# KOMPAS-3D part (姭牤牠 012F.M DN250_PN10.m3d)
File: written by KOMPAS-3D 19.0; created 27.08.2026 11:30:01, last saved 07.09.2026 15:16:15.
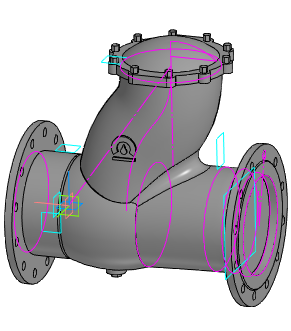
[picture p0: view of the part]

Document properties: Автор: Энергия; Полное имя файла: Z:\3.Личные\kachalov\001_3d для проектировщиков\х.х Тип 012F\012F.M\Клапан 012F.M DN250_PN10.m3d

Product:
- Part/product: (unnamed)  | designation Клапан 012F.M DN250_PN10
    Масса: 181.704

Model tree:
1. Эскиз:1
2. Элемент вращения:1
     Угол 1 = 360
3. Эскиз:2  (with: Элемент вращения:1)
4. Параллельная плоскость:3
5. Эскиз:26
6. Эскиз:30
7. Смещенная плоскость:5
     Расстояние = 150
8. Эскиз:50
9. Эскиз:51
10. Элемент по траектории:1
     Толщина стенки 1 = 1
11. Эскиз:31  (with: Элемент вращения:1)
12. Эскиз:38  (with: Элемент вращения:1)
13. Параллельная плоскость:4
14. Смещенная плоскость:2  (with: Элемент вращения:1)
     Расстояние = 32
15. Эскиз:39  (with: Элемент вращения:1)
16. Эскиз:40  (with: Элемент вращения:1)
17. Смещенная плоскость:3
     Расстояние = 33
18. Эскиз:42  (with: Элемент вращения:1)
19. Элемент по сечениям:4
20. Элемент вращения:6  (with: Элемент вращения:1)
     Угол 1 = 360
21. Эскиз:10  (with: Элемент вращения:1)
22. Элемент выдавливания:3  (with: Элемент вращения:1)
     Расстояние 2 = 19
23. Массив по концентрической сетке:1  (with: Элемент выдавливания:3, Эскиз:10, Элемент вращения:1)  (12 pattern instances)
     Шаг 2 = 360
24. Эскиз:11  (with: Элемент вращения:1)
25. Элемент выдавливания:4  (with: Элемент вращения:1)
     Расстояние 2 = 19
26. Массив по концентрической сетке:2  (with: Элемент выдавливания:4, Эскиз:11, Элемент вращения:1)  (12 pattern instances)
     Шаг 2 = 360
27. Эскиз:32
28. Элемент выдавливания:13
     Расстояние 1 = 25
29. Эскиз:33  (with: Элемент выдавливания:13)
30. Элемент вращения:7
     Угол 1 = 360
31. Эскиз:34  (with: Элемент вращения:1, Элемент вращения:6)
32. Элемент выдавливания:14  (with: Элемент вращения:6)
     Расстояние 1 = 160; Смещение 1 = 10
33. Скругление:23  (with: Элемент выдавливания:14)
     Радиус = 3
34. Эскиз:35  (with: Элемент выдавливания:14)
35. Элемент выдавливания:15
     Расстояние 1 = 10
36. Эскиз:36  (with: Элемент выдавливания:13)
37. Элемент выдавливания:16
     Расстояние 1 = 15
38. Эскиз:43  (with: Элемент выдавливания:13)
39. Массив по концентрической сетке:3  (with: Элемент выдавливания:16, Эскиз:36, Эскиз:33)  (10 pattern instances)
     Шаг 2 = 360
40. Смещенная плоскость:4
     Расстояние = 130
41. Эскиз:46
42. Элемент выдавливания:20  (with: Элемент по траектории:1)
     Расстояние 2 = 4.23072
43. Эскиз:47  (with: Элемент вращения:1)
44. Эскиз:48  (with: Элемент вращения:1)
45. Элемент выдавливания:22
     Расстояние 2 = 320
46. Эскиз:49  (with: Элемент вращения:1)
47. Скругление:28  (with: Элемент по сечениям:4)
     Радиус = 30
48. Скругление:29  (with: Элемент вращения:6)
     Радиус = 20

Expressions: Dn/2; D/2; D2/2; 360/(2*n); 360/(n*2); D3/2
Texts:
  Клапан 012F.M DN250_PN10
